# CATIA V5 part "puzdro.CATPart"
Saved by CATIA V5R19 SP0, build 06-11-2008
Part number: ventilove
Bounding box of the stored display mesh (mm): x -27 to 27, y -14.5 to 14.5, z 0 to 23
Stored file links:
  C:\Users\Jozef Drozd\Desktop\zostava\party\puzdro.CATPart
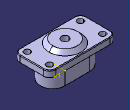
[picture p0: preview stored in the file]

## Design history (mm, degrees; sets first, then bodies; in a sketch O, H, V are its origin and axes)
Body1 (main body)
  Sketch1 on xy-plane, origin (0, 0, 0), H (1, 0, 0), V (0, 1, 0)
    construction line L1 (-10, 0) -> (10, 0)
    line L2 (-10, 10) -> (10, 10)
    line L3 (10, -10) -> (-10, -10)
    arc A1 centre (10, 0) radius 10 from (10, 10) to (10, -10) cw
    arc A2 centre (-10, 0) radius 10 from (-10, -10) to (-10, 10) cw
    distance L1 L2 = 10
    horizontal: L1 H
    tangency: A1 L2, A2 L2, A1 L3, A2 L3
  Pad1: profile Sketch1, direction (0, 0, 1), length 15
  Sketch2 on end face of Pad1, origin (0, 0, 15), H (1, 0, 0), V (0, 1, 0)
    line L1 (-22, 14.5) -> (22, 14.5)
    line L2 (27, 9.5) -> (27, -9.5)
    line L3 (22, -14.5) -> (-22, -14.5)
    line L4 (-27, -9.5) -> (-27, 9.5)
    reference projected line E1 (10, 10) -> (-10, 10) from edge [face of Pad1 from Sketch1.L2 | end face of Pad1]
    reference projected line E2 (-10, -10) -> (10, -10) from edge [face of Pad1 from Sketch1.L3 | end face of Pad1]
    reference projected arc E3 centre (10, 0) radius 10 from (10, -10) to (10, 10) ccw from edge [face of Pad1 from Sketch1.A1 | end face of Pad1]
    arc A1 centre (22, 9.5) radius 5 from (22, 14.5) to (27, 9.5) cw
    arc A2 centre (-22, 9.5) radius 5 from (-22, 14.5) to (-27, 9.5) ccw
    arc A3 centre (22, -9.5) radius 5 from (27, -9.5) to (22, -14.5) cw
    arc A4 centre (-22, -9.5) radius 5 from (-22, -14.5) to (-27, -9.5) cw
    reference projected arc E4 centre (-10, 0) radius 10 from (-10, 10) to (-10, -10) ccw from edge [face of Pad1 from Sketch1.A2 | end face of Pad1]
    distance L1 E1 = 4.5
    distance E2 L3 = 4.5
    distance E3 L2 = 7
    radius A1 = 5
    radius A2 = 5
    radius A3 = 5
    radius A4 = 5
    distance E4 L4 = 7
    horizontal: L1 H, L3 H
    vertical: L2 V, L4 V
    tangency: A1 L1, A1 L2, A2 L1, A2 L4, A3 L2, A3 L3, A4 L3, A4 L4
  Pad2: profile Sketch2, direction (0, 0, 1), length 5
  Sketch3 on end face of Pad2, origin (0, 0, 20), H (1, 0, 0), V (0, 1, 0)
    circle A1 centre (0, 0) radius 3
  Pocket1: profile Sketch3, direction (0, 0, -1), length 20
  Sketch4 on start face of Pad1, origin (0, 0, 0), H (1, 0, 0), V (0, -1, 0)
    construction line L1 (-10, 0) -> (10, 0)
    point P1 (-10, 0)
    line L2 (-10, 9) -> (10, 9)
    line L3 (10, -9) -> (-10, -9)
    arc A1 centre (10, 0) radius 9 from (10, 9) to (10, -9) cw
    arc A2 centre (-10, 0) radius 9 from (-10, -9) to (-10, 9) cw
    distance L1 L2 = 9
    coincidence: P1 H
    horizontal: L1 H
    tangency: A1 L2, A2 L2, A1 L3, A2 L3
  Pocket2: profile Sketch4, direction (0, 0, 1), length 0.5
  Sketch5 on end face of Pocket2, origin (0, 0, 0.5), H (1, 0, 0), V (0, -1, 0)
    point P1 (8, 0)
    coincidence: P1 H
  Chamfer1: length 5, angle 45, on edge [end face of Pocket2 | face of Pocket1 from Sketch3.A1]
  Fillet1: radius 5, on edge [face of Chamfer1 | face of Pocket1 from Sketch3.A1]; edge [end face of Pocket2 | face of Chamfer1]
  Sketch6 on end face of Pad2, origin (0, 0, 20), H (1, 0, 0), V (0, 1, 0)
    circle A1 centre (0, 0) radius 10
    point P1 (10, 0)
    circle A2 centre (0, 0) radius 3
    point P2 (3, 0)
    coincidence: A1 P1, P1 H, A2 P2, P2 H
  Pad3: profile Sketch6, direction (0, 0, 1), length 3
  Chamfer2: length 3, angle 45, on edge [end face of Pad2 | face of Pad3 from Sketch6.A1]
  Sketch7 on end face of Pad2, origin (0, 0, 20), H (1, 0, 0), V (0, 1, 0)
    circle A1 centre (-21.5, 9) radius 2.5
    circle A2 centre (21.5, 9) radius 2.5
    circle A3 centre (-21.5, -9) radius 2.5
    circle A4 centre (21.5, -9) radius 2.5
    reference projected line E1 (-27, 10.5) -> (-27, -10.5) from edge [face of Pad2 from Sketch2.L4 | end face of Pad2]
    reference projected line E2 (23, 14.5) -> (-23, 14.5) from edge [face of Pad2 from Sketch2.L1 | end face of Pad2]
    distance A1 E1 = 3
    distance A1 E2 = 3
    radius A1 = 2.5
    symmetry: A1 A2 V, A1 A3 H, A2 A4 H
  Pocket3: profile Sketch7, direction (0, 0, -1), length 5
  Chamfer3: length 1, angle 45, on edge [face of Pad1 from Sketch1.A2 | start face of Pad2]; edge [face of Pad1 from Sketch1.L3 | start face of Pad2]; edge [face of Pad1 from Sketch1.A1 | start face of Pad2]; edge [face of Pad1 from Sketch1.L2 | start face of Pad2]
  Chamfer4: length 0.5, angle 45, on edge [face of Pad2 from Sketch2.L2 | end face of Pad2]; edge [face of Pad2 from Sketch2.A3 | end face of Pad2]; edge [face of Pad2 from Sketch2.L3 | end face of Pad2]; edge [face of Pad2 from Sketch2.A1 | end face of Pad2]; edge [face of Pad2 from Sketch2.L1 | end face of Pad2]; edge [face of Pad2 from Sketch2.A2 | end face of Pad2]; edge [face of Pad2 from Sketch2.L4 | end face of Pad2]; edge [face of Pad2 from Sketch2.A4 | end face of Pad2]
